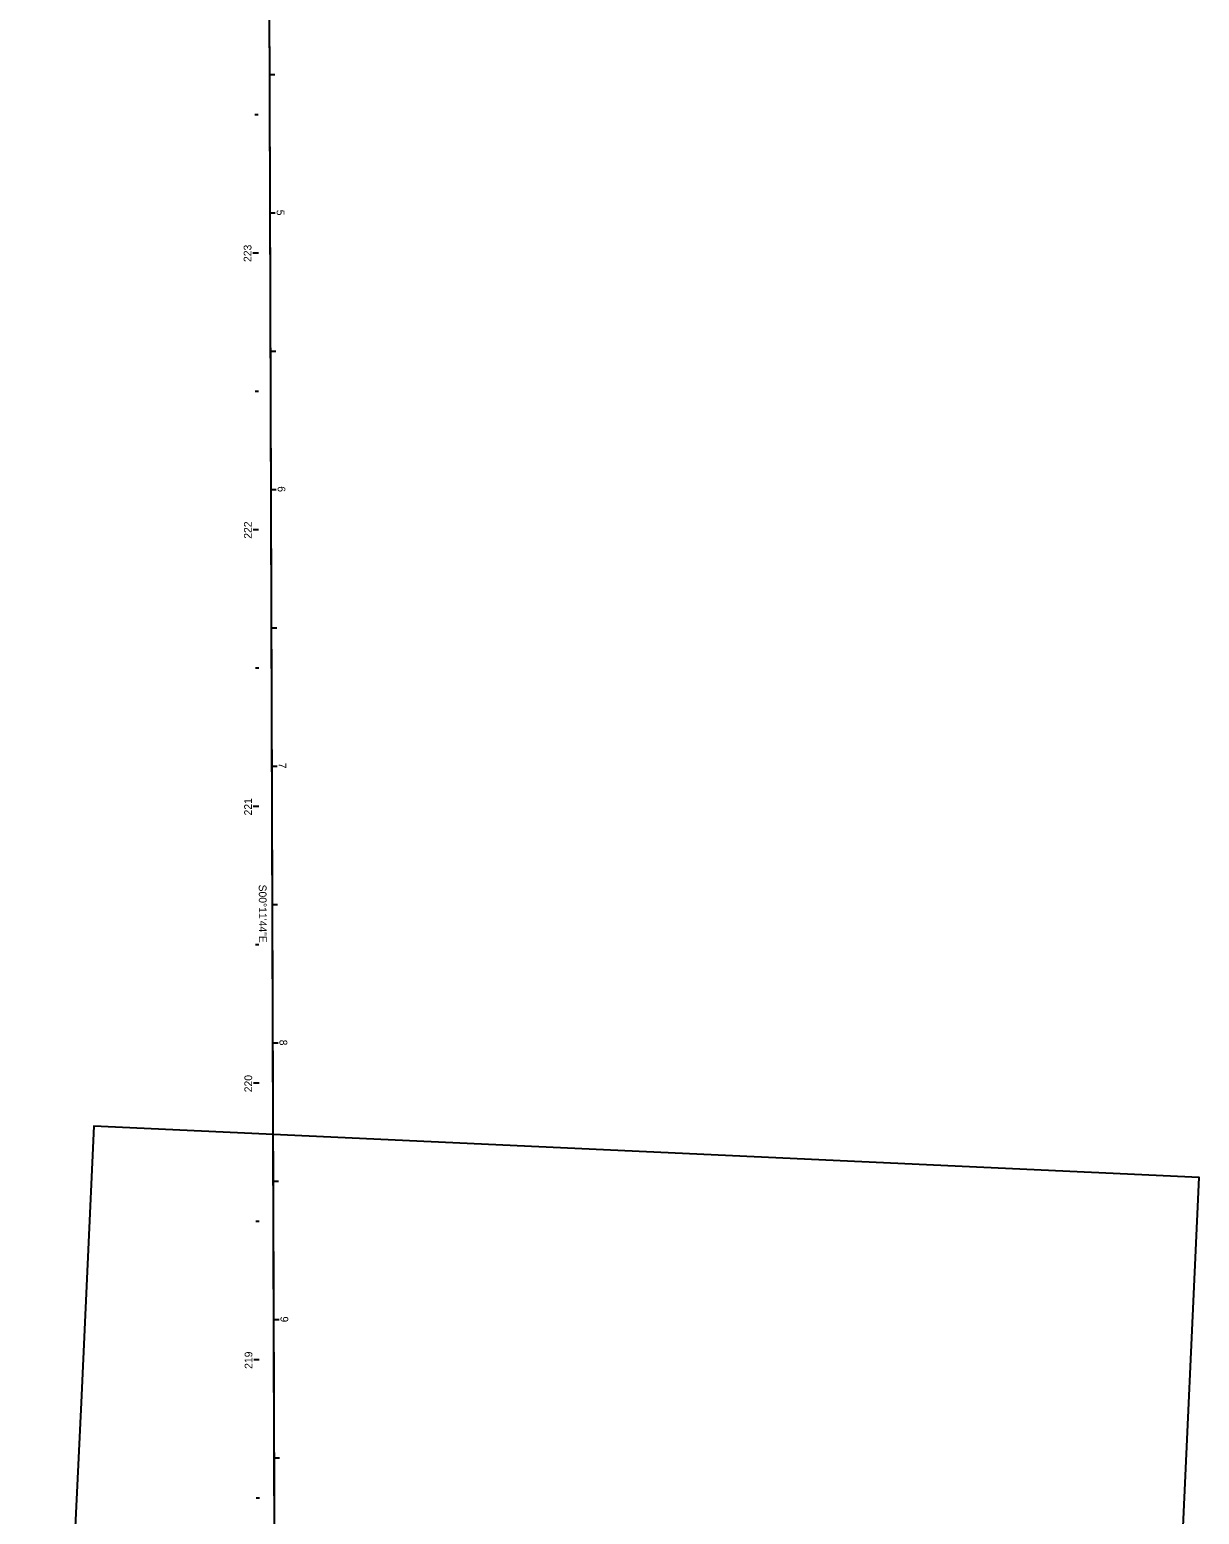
# Model space of a CAD drawing. Extents: x 172043 to 172958, y 249504 to 260295.
# Drawn here: x 172428 to 172851, y 258766 to 259303 of the extents above; entities that cross this region are included whole.
import ezdxf

# ---------------------------------------------------------------- set-up
doc = ezdxf.new("R2010")
doc.units = 0
for name, color, linetype in [('DR_X_Storm_Sewer', 7, 'Continuous'), ('PV_X_EOP', 7, 'Continuous'), ('SC_Scratch1', 7, 'Continuous')]:
    doc.layers.add(name, color=color, linetype=linetype)

msp = doc.modelspace()

# ---------------------------------------------------------------- linework, layer by layer
at = {"layer": 'DR_X_Storm_Sewer'}
msp.add_lwpolyline([(172428.41, 258406.85), (172827.98, 258388.27), (172830.3, 258438.22), (172832.63, 258488.16), (172834.95, 258538.11), (172837.27, 258588.06), (172839.59, 258638), (172841.92, 258687.95), (172844.24, 258737.89), (172846.56, 258787.84), (172848.88, 258837.79), (172851.21, 258887.73), (172451.64, 258906.31), (172449.32, 258856.37), (172446.99, 258806.42), (172444.67, 258756.48), (172442.35, 258706.53), (172440.03, 258656.58), (172437.7, 258606.64), (172435.38, 258556.69), (172433.06, 258506.75), (172430.74, 258456.8)], close=True, dxfattribs=at)
at = {"layer": 'PV_X_EOP'}
for p, q in [((172511.04, 259271.83), (172509.84, 259271.83)), ((172511.08, 259221.83), (172509.08, 259221.83)), ((172511.12, 259171.83), (172509.92, 259171.83)), ((172511.16, 259121.83), (172509.16, 259121.83)), ((172511.2, 259071.83), (172510, 259071.83)), ((172511.24, 259021.83), (172509.24, 259021.83)), ((172511.28, 258971.83), (172510.08, 258971.83)), ((172511.33, 258921.83), (172509.33, 258921.83)), ((172511.37, 258871.83), (172510.17, 258871.83)), ((172511.41, 258821.83), (172509.41, 258821.83)), ((172511.45, 258771.83), (172510.25, 258771.83))]:
    msp.add_line(p, q, dxfattribs=at)
at = {"layer": 'SC_Scratch1'}
for p, q in [((172513.49, 259736.44), (172516.79, 258770.25)), ((172513.49, 259736.44), (172518.63, 258228.95)), ((172515.02, 259286.44), (172517.02, 259286.45)), ((172515.2, 259236.44), (172517.2, 259236.45)), ((172515.37, 259186.44), (172517.37, 259186.45)), ((172515.54, 259136.44), (172517.54, 259136.45)), ((172515.71, 259086.44), (172517.71, 259086.45)), ((172515.88, 259036.44), (172517.88, 259036.45)), ((172516.05, 258986.44), (172518.05, 258986.45)), ((172516.22, 258936.44), (172518.22, 258936.45)), ((172516.39, 258886.44), (172518.39, 258886.45)), ((172516.56, 258836.44), (172518.56, 258836.45)), ((172516.73, 258786.44), (172518.73, 258786.45))]:
    msp.add_line(p, q, dxfattribs=at)

# ---------------------------------------------------------------- texts
at = {"layer": 'PV_X_EOP'}
for s, p in [('223', (172508.58, 259218.63)), ('222', (172508.67, 259118.62)), ('221', (172508.75, 259018.61)), ('220', (172508.83, 258918.56)), ('219', (172508.91, 258818.6))]:
    msp.add_text(s, height=2.8, rotation=90.0466, dxfattribs=at).set_placement(p)
at = {"layer": 'SC_Scratch1'}
for s, p in [('5', (172517.69, 259237.52)), ('6', (172518.03, 259137.57)), ('7', (172518.37, 259037.63)), ('S00°11\'44"E', (172511.22, 258993.61)), ('8', (172518.71, 258937.55)), ('9', (172519.06, 258837.54))]:
    msp.add_text(s, height=2.8, rotation=270.1955, dxfattribs=at).set_placement(p)

doc.saveas('drawing.dxf')
